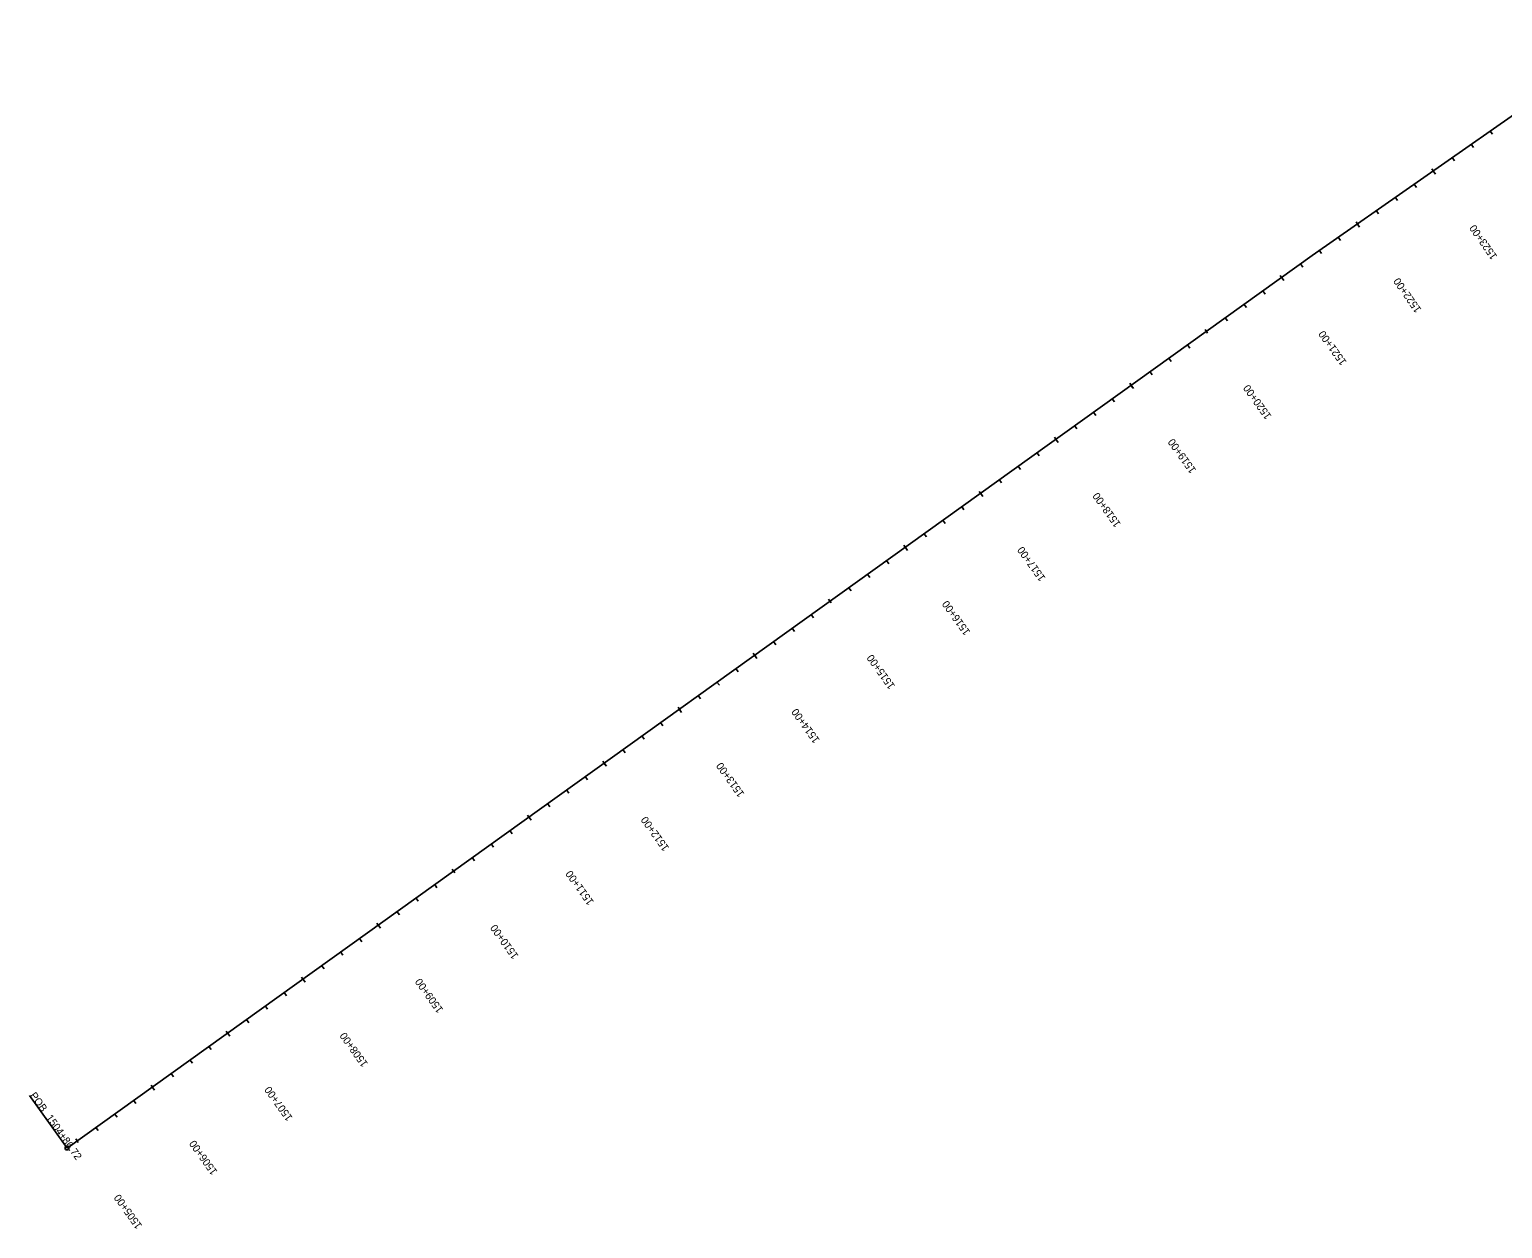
# Model space of a CAD drawing. Extents: x 11280201 to 11283391, y 9498969 to 9501722.
# Drawn here: x 11280201 to 11281791, y 9498969 to 9500264 of the extents above; entities that cross this region are included whole.
import ezdxf

# ---------------------------------------------------------------- set-up
doc = ezdxf.new("R2010")
doc.units = 0
for name, color, linetype in [('PS_BOLT', 7, 'Continuous'), ('PS_DIM', 7, 'Continuous'), ('PS_MID', 7, 'Continuous'), ('PS_SHAPE', 7, 'Continuous')]:
    doc.layers.add(name, color=color, linetype=linetype)

msp = doc.modelspace()

# ---------------------------------------------------------------- linework, layer by layer
at = {"layer": 'PS_BOLT'}
for p, q in [((11281716.2, 9500110.9), (11281718.7, 9500107.3)), ((11281634.2, 9500053.7), (11281636.7, 9500050.1)), ((11281552.5, 9499996), (11281555, 9499992.5)), ((11281469.8, 9499939.7), (11281472.6, 9499935.8)), ((11281389.9, 9499879.5), (11281392.5, 9499875.9)), ((11281308.6, 9499821.2), (11281311.2, 9499817.7)), ((11281227.4, 9499763), (11281229.9, 9499759.4)), ((11281146.1, 9499704.7), (11281148.6, 9499701.1)), ((11281063.4, 9499648.4), (11281066.3, 9499644.4)), ((11280983.6, 9499588.2), (11280986.1, 9499584.6)), ((11280902.3, 9499529.9), (11280904.8, 9499526.3)), ((11280821, 9499471.6), (11280823.6, 9499468.1)), ((11280739.7, 9499413.4), (11280742.3, 9499409.8)), ((11280657, 9499357.1), (11280659.9, 9499353.1)), ((11280577.2, 9499296.8), (11280579.7, 9499293.3)), ((11280495.9, 9499238.6), (11280498.5, 9499235)), ((11280414.7, 9499180.3), (11280417.2, 9499176.7)), ((11280333.4, 9499122), (11280335.9, 9499118.5)), ((11280250.7, 9499065.8), (11280253.5, 9499061.8))]:
    msp.add_line(p, q, dxfattribs=at)
at = {"layer": 'PS_DIM'}
msp.add_line((11280241.3, 9499056), (11280200.8, 9499112.6), dxfattribs=at)
msp.add_circle((11280241.3, 9499056), 2.14, dxfattribs=at)
at = {"layer": 'PS_MID'}
for p, q in [((11281777.7, 9500153.8), (11281780.2, 9500150.3)), ((11281757.2, 9500139.5), (11281759.7, 9500136)), ((11281736.7, 9500125.2), (11281739.2, 9500121.6)), ((11281714.8, 9500112.9), (11281717.6, 9500108.9)), ((11281675.2, 9500082.3), (11281677.7, 9500078.7)), ((11281695.7, 9500096.6), (11281698.2, 9500093)), ((11281654.7, 9500068), (11281657.2, 9500064.4)), ((11281632.8, 9500055.7), (11281635.6, 9500051.7)), ((11281613.7, 9500039.4), (11281616.2, 9500035.8)), ((11281593.2, 9500025.1), (11281595.7, 9500021.5)), ((11281572.8, 9500010.6), (11281575.3, 9500007)), ((11281551, 9499998), (11281553.9, 9499994)), ((11281532.1, 9499981.5), (11281534.7, 9499977.9)), ((11281511.8, 9499966.9), (11281514.4, 9499963.3)), ((11281469.8, 9499939.7), (11281472.6, 9499935.8)), ((11281491.5, 9499952.3), (11281494, 9499948.8)), ((11281450.9, 9499923.2), (11281453.4, 9499919.6)), ((11281430.6, 9499908.6), (11281433.1, 9499905.1)), ((11281410.2, 9499894.1), (11281412.8, 9499890.5)), ((11281388.5, 9499881.5), (11281391.3, 9499877.5)), ((11281369.6, 9499864.9), (11281372.1, 9499861.4)), ((11281349.3, 9499850.4), (11281351.8, 9499846.8)), ((11281329, 9499835.8), (11281331.5, 9499832.2)), ((11281307.2, 9499823.2), (11281310.1, 9499819.2)), ((11281288.3, 9499806.7), (11281290.9, 9499803.1)), ((11281268, 9499792.1), (11281270.6, 9499788.5)), ((11281225.9, 9499764.9), (11281228.8, 9499761)), ((11281247.7, 9499777.5), (11281250.2, 9499774)), ((11281207.1, 9499748.4), (11281209.6, 9499744.8)), ((11281186.7, 9499733.8), (11281189.3, 9499730.3)), ((11281166.4, 9499719.3), (11281169, 9499715.7)), ((11281144.7, 9499706.7), (11281147.5, 9499702.7)), ((11281125.8, 9499690.1), (11281128.3, 9499686.6)), ((11281105.5, 9499675.6), (11281108, 9499672)), ((11281085.1, 9499661), (11281087.7, 9499657.4)), ((11281063.4, 9499648.4), (11281066.3, 9499644.4)), ((11281044.5, 9499631.9), (11281047.1, 9499628.3)), ((11281024.2, 9499617.3), (11281026.7, 9499613.7)), ((11280982.1, 9499590.1), (11280985, 9499586.2)), ((11281003.9, 9499602.7), (11281006.4, 9499599.2)), ((11280963.2, 9499573.6), (11280965.8, 9499570)), ((11280942.9, 9499559), (11280945.5, 9499555.5)), ((11280922.6, 9499544.5), (11280925.1, 9499540.9)), ((11280900.9, 9499531.9), (11280903.7, 9499527.9)), ((11280882, 9499515.3), (11280884.5, 9499511.8)), ((11280861.7, 9499500.8), (11280864.2, 9499497.2)), ((11280841.3, 9499486.2), (11280843.9, 9499482.6)), ((11280819.6, 9499473.6), (11280822.4, 9499469.6)), ((11280800.7, 9499457.1), (11280803.2, 9499453.5)), ((11280780.4, 9499442.5), (11280782.9, 9499438.9)), ((11280738.3, 9499415.3), (11280741.2, 9499411.4)), ((11280760.1, 9499427.9), (11280762.6, 9499424.4)), ((11280719.4, 9499398.8), (11280722, 9499395.2)), ((11280699.1, 9499384.2), (11280701.7, 9499380.7)), ((11280678.8, 9499369.7), (11280681.3, 9499366.1)), ((11280657, 9499357.1), (11280659.9, 9499353.1)), ((11280638.2, 9499340.5), (11280640.7, 9499337)), ((11280617.8, 9499326), (11280620.4, 9499322.4)), ((11280597.5, 9499311.4), (11280600.1, 9499307.8)), ((11280575.8, 9499298.8), (11280578.6, 9499294.8)), ((11280556.9, 9499282.3), (11280559.4, 9499278.7)), ((11280536.6, 9499267.7), (11280539.1, 9499264.1)), ((11280494.5, 9499240.6), (11280497.4, 9499236.6)), ((11280516.2, 9499253.1), (11280518.8, 9499249.6)), ((11280475.6, 9499224), (11280478.2, 9499220.4)), ((11280455.3, 9499209.4), (11280457.8, 9499205.9)), ((11280435, 9499194.9), (11280437.5, 9499191.3)), ((11280413.2, 9499182.3), (11280416.1, 9499178.3)), ((11280394.3, 9499165.7), (11280396.9, 9499162.2)), ((11280374, 9499151.2), (11280376.6, 9499147.6)), ((11280353.7, 9499136.6), (11280356.2, 9499133)), ((11280332, 9499124), (11280334.8, 9499120)), ((11280313.1, 9499107.5), (11280315.6, 9499103.9)), ((11280292.7, 9499092.9), (11280295.3, 9499089.3)), ((11280250.7, 9499065.8), (11280253.5, 9499061.8)), ((11280272.4, 9499078.3), (11280275, 9499074.8))]:
    msp.add_line(p, q, dxfattribs=at)
at = {"layer": 'PS_SHAPE'}
for p, q in [((11281585.4, 9500019.6), (11281934.7, 9500263.5)), ((11280241.3, 9499056), (11281585.4, 9500019.6))]:
    msp.add_line(p, q, dxfattribs=at)

# ---------------------------------------------------------------- texts
at = {"layer": 'PS_BOLT'}
for s, p in [('1520+00', (11281541.9, 9499846.2)), ('1515+00', (11281135.5, 9499554.9)), ('1510+00', (11280729.1, 9499263.5)), ('1505+00', (11280322.8, 9498972.2))]:
    msp.add_text(s, height=8.16, rotation=125.6379, dxfattribs=at).set_placement(p)
at = {"layer": 'PS_DIM'}
for s, p in [('POB ', (11280200.9, 9499112.7)), ('1504+86.72', (11280218.2, 9499088.6))]:
    msp.add_text(s, height=8.02, rotation=305.6379, dxfattribs=at).set_placement(p)
at = {"layer": 'PS_MID'}
for s, rotation, p in [('1523+00', 124.919, (11281785.7, 9500018.5)), ('1522+00', 124.919, (11281703.7, 9499961.2)), ('1521+00', 125.6379, (11281623.1, 9499904.5)), ('1520+00', 125.6379, (11281541.9, 9499846.2)), ('1519+00', 125.6379, (11281460.6, 9499787.9)), ('1518+00', 125.6379, (11281379.3, 9499729.7)), ('1517+00', 125.6379, (11281298, 9499671.4)), ('1516+00', 125.6379, (11281216.8, 9499613.1)), ('1515+00', 125.6379, (11281135.5, 9499554.9)), ('1514+00', 125.6379, (11281054.2, 9499496.6)), ('1513+00', 125.6379, (11280973, 9499438.3)), ('1512+00', 125.6379, (11280891.7, 9499380.1)), ('1511+00', 125.6379, (11280810.4, 9499321.8)), ('1510+00', 125.6379, (11280729.1, 9499263.5)), ('1509+00', 125.6379, (11280647.9, 9499205.3)), ('1508+00', 125.6379, (11280566.6, 9499147)), ('1507+00', 125.6379, (11280485.3, 9499088.7)), ('1506+00', 125.6379, (11280404.1, 9499030.5)), ('1505+00', 125.6379, (11280322.8, 9498972.2))]:
    msp.add_text(s, height=8.16, rotation=rotation, dxfattribs=at).set_placement(p)

doc.saveas('drawing.dxf')
